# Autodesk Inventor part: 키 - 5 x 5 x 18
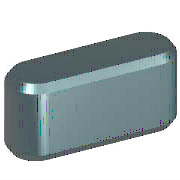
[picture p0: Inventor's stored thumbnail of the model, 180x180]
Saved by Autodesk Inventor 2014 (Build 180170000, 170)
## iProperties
Created: 2012-02
Part Number: 키 - 5 x 5 x 18
Material: 강철, 연강
Description: 키 및 해당 키홈
Document SubType Name: Modeling
Standard: KS B 1311
Designer: mduedu
Standards Organization: KS
Language: ko-KR
Size Designation: 5 x 5 x 18
Categories: <MemberInstance><Categories><Category DisplayName="샤프트 부품" InternalName="7f7aeb1f-a693-4053-b835-cee3144e0d98" Mnemonic="SHFT"><Category DisplayName="키" Interna
Density: 7.86 g/cm^3
Appearance: 매끄러움 - 노란색
Mass: 3.27476 g
Surface Area: 3.57848 cm^2
Volume: 0.416636 cm^3
IsCustomPart: 1
Author: mduedu
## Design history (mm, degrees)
workplane "Work Plane1"
workplane "Work Plane2"
sketch "스케치1"
  geometry: L1 (2.5, 2.5)-(15.5, 2.5); L2 (15.5, -2.5)-(2.5, -2.5); L3 (0, 9.4)-(0, -7.4) reference; L4 (-5, 0)-(30, 0) reference; L5 (18, 0)-(18, 7); A1 r 2.5 centre (2.5, 0) between (2.5, 2.5) and (2.5, -2.5); A2 r 2.5 centre (15.5, 0) between (15.5, -2.5) and (15.5, 2.5)
  constraints: 6 end point, 5 point on circle, 4 tangent, 3 point on line, 2 centre point, 1 horizontal, 1 parallel, 1 perpendicular
  dimensions: "d0" = 2.5 radius of A1 (= 0.5 x PB); "d13" = 2.5 radius of A2 (= 0.5 x PB); "d14" = 18 distance between parallel lines of L5 L3 (= NLG)
extrude "본체1" new body sketch "스케치1" taper "d3" = 0 deg; stored distance "d4" = 10
workplane "Work Plane3"
body "Solid1"
chamfer "모따기1" distance "d8" = 0.4 (= PHH); stored, may be unused: second distance "d9" = 0.4 (= PHH), angle "d15" = 45 deg
other parameters: "d1" = -3 (= -PNT), "d2" = 2 (= PH - PNT), "NLG" = 18 [user parameter; used in 3 equation terms], "PB" = 5 [user parameter; used in 2 equation terms], "PNT" = 3 [user parameter; used in 2 equation terms], "PH" = 5 [user parameter; used in 1 equation term], "PHH" = 0.4 [user parameter; used in 2 equation terms], "d10" = 0, "d16" = 0, "d17" = 0, "d18" = 0, "WDMIN" = 12 [user parameter], "PLB2" = 18 (= NLG) [user parameter], "WDMAX" = 17 [user parameter], "PLB1" = 18 (= NLG) [user parameter], "RR" = 0.16 [user parameter], "PUEB" = 2.3 [user parameter]
